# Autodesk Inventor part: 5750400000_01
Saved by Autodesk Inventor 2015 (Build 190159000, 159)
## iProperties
Created: 2020-07
Part Number: 5750400000_01
Checked By: TraceParts S.A.
Material: Generic
Catalog Web Link: www.traceparts.com
Document SubType Name: Modeling
Designer: TraceParts
Density: 1 g/cm^3
Appearance: Default
Company: TraceParts S.A.
Author: TraceParts
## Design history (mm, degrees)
feature "5750400000_01.ipt"
body "Solid1"
